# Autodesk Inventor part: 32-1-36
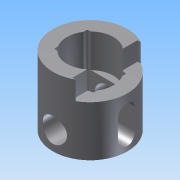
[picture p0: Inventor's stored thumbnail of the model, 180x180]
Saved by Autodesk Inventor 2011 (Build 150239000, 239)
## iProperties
Created: 2014-02
Part Number: 32-1-36
Document SubType Name: Modeling
Designer: Administrator
Density: 1 g/cm^3
Author: Administrator
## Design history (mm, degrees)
sketch "草图1"
  geometry: C1 r 20 at (0, 0); 1 further point
  constraints: 1 centre point, 1 coincident
  dimensions: "d0" = 40 diameter of C1
extrude "拉伸1" new body sketch "草图1" distance "d1" = 37; taper "d2" = 0 deg
sketch "草图2"
  geometry: L1 (-10.5, -9)-(10.5, -9); L2 (10.5, -9)-(10.5, 9); L3 (10.5, 9)-(-10.5, 9); L4 (-10.5, 9)-(-10.5, -9); C1 r 20 at (0, 0) reference; 2 further points
  constraints: 8 end point, 2 midpoint, 2 parallel, 1 horizontal, 1 horizontal alignment, 1 perpendicular, 1 vertical alignment
  dimensions: "d3" = 21 distance of L1.start L1.end; "d4" = 18 distance of L1.end L2.end
extrude "拉伸2" cut sketch "草图2" stored distance "d5" = 18; taper "d6" = 0 deg
hole "Hole1" diameter "d9" = 25; stored, may be unused: countersink angle "d13" = 90 deg, drill point angle "d15" = 0 deg; dims "d7" = 10, "d8" = 10, "d10" = 6, "d11" = 4, "d12" = 2, "d14" = 18
node "工作平面1"
sketch "草图3"
  geometry: L1 (-20, 0)-(20, 0) reference; C1 r 6.5 at (0, 10); 2 further points
  constraints: 1 centre point, 1 coincident
  dimensions: "d17" = 13 diameter of C1; "d18" = 10 distance of C1.centre point (0, 0)
extrude "拉伸3" cut sketch "草图3" stored distance "d19" = 18; taper "d20" = 0 deg
node "工作平面2"
sketch "草图4"
  geometry: L1 (-20, 0)-(20, 0) reference; L2 (-4.5, 7)-(-4.5, 12.5); L3 (4.5, 7)-(4.5, 12.5); L4 (-4.5, 18)-(-4.5, 12.5); L5 (4.5, 18)-(4.5, 12.5); A1 r 4.5 centre (0, 7) between (-4.5, 7) and (4.5, 7); A2 r 4.5 centre (0, 18) between (4.5, 18) and (-4.5, 18); 1 further point
  constraints: 8 end point, 4 point on circle, 2 centre point, 2 tangent, 1 parallel, 1 perpendicular
  dimensions: "d22" = 9 diameter of A1; "d23" = 7 distance of point (0, 0) A1.centre; "d24" = 5.5 distance of L2.start L2.end
extrude "拉伸4" cut sketch "草图4" stored distance "d25" = 18; taper "d26" = 0 deg
sketch "草图5"
  geometry: L1 (8, -17.5)-(20, -17.5); L2 (20, -17.5)-(20, 17.5); L3 (20, 17.5)-(8, 17.5); L4 (8, 17.5)-(8, -17.5); A1 r 12.5 centre (0, 0) between (-10.5, 6.782) and (-10.5, -6.782) reference; A2 r 12.5 centre (0, 0) between (8.675, 9) and (-8.675, 9) reference; 1 further point
  constraints: 8 end point, 2 parallel, 1 horizontal, 1 horizontal alignment, 1 midpoint, 1 perpendicular
  dimensions: "d27" = 8 distance from line of A2.centre L4; "d30" = 35 distance of L1.end L2.end; "d31" = 12 distance of L2.end L3.end
extrude "拉伸5" cut sketch "草图5" distance "d28" = 10; taper "d29" = 0 deg
fillet "圆角1" dims "d32" = 0.8
node "实体1"
